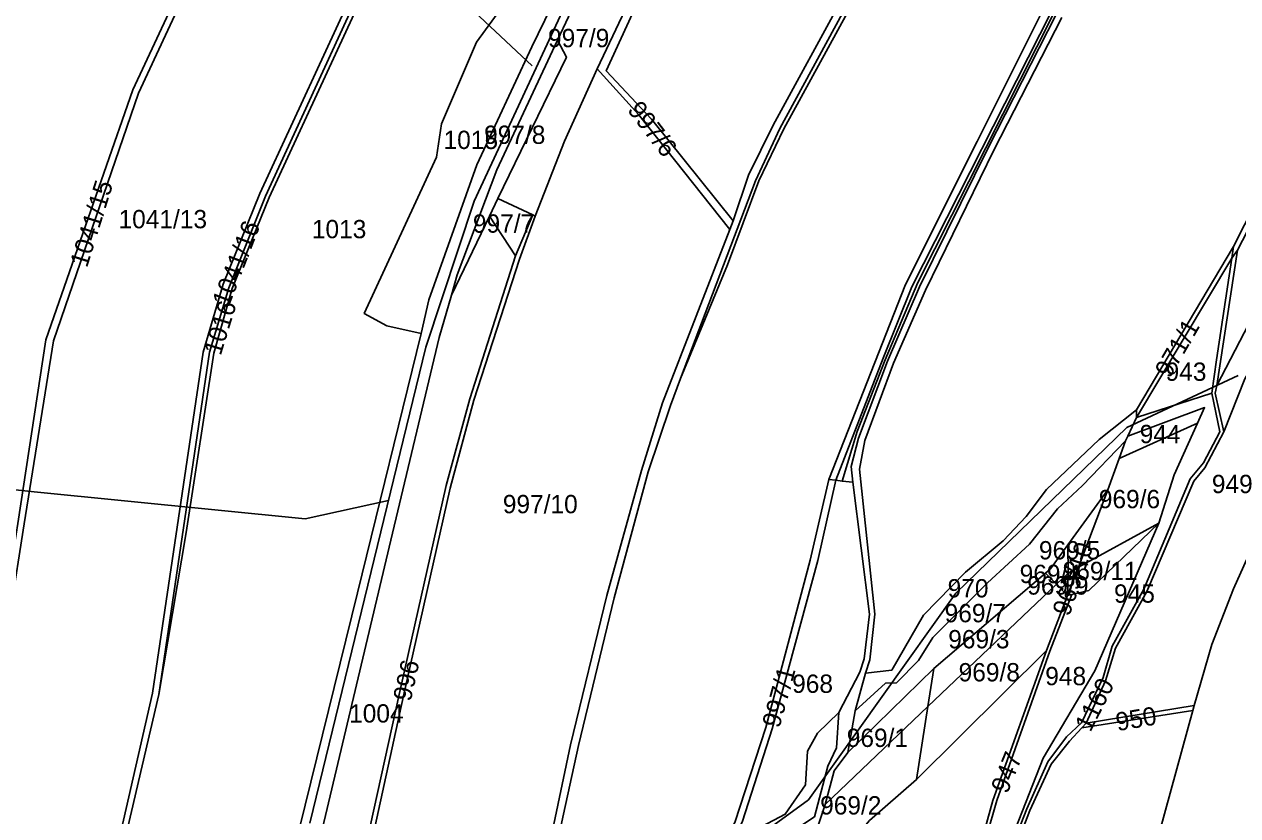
# Model space of a CAD drawing. Extents: x -623250 to -619626, y -1079612 to -1075424.
# Drawn here: x -622122 to -621459, y -1078639 to -1078207 of the extents above; entities that cross this region are included whole.
import ezdxf

# ---------------------------------------------------------------- set-up
doc = ezdxf.new("R2010")
doc.units = 0
for name, color, linetype in [('Cestní síť', 7, 'Continuous'), ('Parcela nároku', 7, 'Continuous'), ('Parcelní číslo', 7, 'Continuous'), ('Silnice III_35719', 7, 'Continuous'), ('Technická opateření liniová', 7, 'Continuous')]:
    doc.layers.add(name, color=color, linetype=linetype)

msp = doc.modelspace()

# ---------------------------------------------------------------- linework, layer by layer
at = {"layer": 'Cestní síť'}
for p, q in [((-621519.46, -1078427.24), (-621458.59, -1078398.76)), ((-621612.73, -1078517.62), (-621519.46, -1078427.24)), ((-622116.23, -1078462.32), (-622408.06, -1078432)), ((-621968.13, -1078477.07), (-622116.23, -1078462.32)), ((-621968.13, -1078477.07), (-621922.63, -1078467.15)), ((-621693.23, -1078630.58), (-621612.73, -1078517.62)), ((-621746.25, -1078668.89), (-621693.23, -1078630.58))]:
    msp.add_line(p, q, dxfattribs=at)
at = {"layer": 'Parcela nároku'}
for points in [[(-621287.56, -1077905.65), (-621340.92, -1078060.83), (-621413.47, -1078234.45), (-621461.2, -1078328.4), (-621462.02, -1078334.75), (-621459.02, -1078330.44), (-621410.27, -1078236.51), (-621337.32, -1078062), (-621284.16, -1077906.18), (-621257.6, -1077825.18), (-621204.75, -1077662.32), (-621198.6, -1077626.58), (-621199.7, -1077617.03), (-621206.08, -1077609.32), (-621211.44, -1077608.6), (-621204.6, -1077618.06), (-621201.95, -1077630.34), (-621208.08, -1077659.7), (-621260.76, -1077824.45)], [(-621364.39, -1077678.9), (-621360.94, -1077671.33), (-621356.07, -1077656.62), (-621361.81, -1077680.91), (-621375.21, -1077712.24), (-621395.2, -1077773.48), (-621413.63, -1077833.01), (-621448.87, -1077932.09), (-621484.15, -1078031.22), (-621531.47, -1078143.68), (-621559.31, -1078200.97), (-621633.61, -1078348.03), (-621651.3, -1078390.37), (-621666.67, -1078429.48), (-621674.85, -1078456.45), (-621678.32, -1078456.03), (-621652.48, -1078389.36), (-621636.77, -1078350.51), (-621560.48, -1078200.14), (-621532.5, -1078143.13), (-621485.18, -1078030.89), (-621450, -1077931.7), (-621414.98, -1077832.91), (-621377.7, -1077716.06)], [(-621536.14, -1078141.02), (-621489.42, -1078030.25), (-621424.75, -1077849.92), (-621379.95, -1077714.81), (-621377.7, -1077716.06), (-621414.98, -1077832.91), (-621450, -1077931.7), (-621485.18, -1078030.89), (-621532.5, -1078143.13), (-621560.48, -1078200.14), (-621636.77, -1078350.51), (-621652.48, -1078389.36), (-621678.32, -1078456.03), (-621682.14, -1078455.7), (-621640.24, -1078349.18), (-621601.13, -1078271)], [(-621722.01, -1078071.14), (-621688.22, -1078002.49), (-621678.81, -1077968.47), (-621662.8, -1077941.45), (-621649.7, -1077951.64), (-621639.49, -1077964.79), (-621623.87, -1077987.92), (-621612.61, -1077986.75), (-621607.21, -1077988.04), (-621600.75, -1078000.02), (-621600.73, -1078020.83), (-621618.53, -1078069.92), (-621649.86, -1078144.65), (-621673.38, -1078190.19), (-621712.52, -1078262.15), (-621725.93, -1078289.46), (-621734.43, -1078314.47), (-621779.01, -1078258.82), (-621803.7, -1078232.45), (-621772.94, -1078165.3)], [(-621817.29, -1077954.75), (-621820.07, -1077956.12), (-621837.79, -1077997.65), (-621875.7, -1078069.47), (-621917.7, -1078144.04), (-621989.81, -1078300.86), (-622009.81, -1078350.99), (-622020.37, -1078386.11), (-622048.13, -1078572.96), (-622033.09, -1078484.64), (-622018.08, -1078386.56), (-622007.96, -1078351.4), (-621987.87, -1078301.69), (-621915.38, -1078144.86), (-621873.83, -1078070.23), (-621835.8, -1077998.21)], [(-621830.83, -1078167.93), (-621842.45, -1078186.44), (-621849.93, -1078182.93), (-621874.57, -1078216.88), (-621893.72, -1078261.43), (-621896.45, -1078279.61), (-621935.88, -1078364.97), (-621923.56, -1078371.78), (-621904.78, -1078375.94), (-621900.59, -1078357.45), (-621874.38, -1078283.8), (-621844.4, -1078219.47), (-621798.7, -1078125.48)], [(-621800.25, -1078151.95), (-621830.24, -1078215.74), (-621825.45, -1078225.11), (-621862.83, -1078302.15), (-621843.79, -1078311.14), (-621842.49, -1078311.78), (-621826.5, -1078270.98), (-621808.67, -1078231.35), (-621776.45, -1078163.32)], [(-621779.01, -1078258.82), (-621734.43, -1078314.47), (-621736.18, -1078319.06), (-621786.12, -1078256.36), (-621808.67, -1078231.35), (-621776.45, -1078163.32), (-621772.94, -1078165.3), (-621803.7, -1078232.45)], [(-621830.24, -1078215.74), (-621863.53, -1078286.56), (-621885.08, -1078343.91), (-621888.3, -1078355.01), (-621867.46, -1078311.76), (-621862.83, -1078302.15), (-621825.45, -1078225.11)], [(-621851, -1078335.41), (-621875.98, -1078412.38), (-621889.02, -1078460.29), (-621914.51, -1078573.82), (-621939.52, -1078688.9), (-621916.93, -1078683.27), (-621862.33, -1078678.06), (-621842.5, -1078672.85), (-621836.88, -1078665.49), (-621823.3, -1078600.54), (-621803.29, -1078519.05), (-621784.46, -1078450.78), (-621772.93, -1078413.68), (-621736.18, -1078319.06), (-621786.12, -1078256.36), (-621808.67, -1078231.35), (-621826.5, -1078270.98), (-621842.49, -1078311.78)], [(-621340.16, -1078254.66), (-621336.49, -1078264.69), (-621353.63, -1078275.14), (-621364.04, -1078283.5), (-621372.09, -1078295.2), (-621389.85, -1078310.39), (-621432.54, -1078360.91), (-621455.01, -1078400.57), (-621466.37, -1078429.55), (-621471.07, -1078408.51), (-621470.26, -1078404.27), (-621452.78, -1078370.63), (-621435.04, -1078346.86), (-621398.92, -1078305.09), (-621366.28, -1078263.93), (-621348.2, -1078261.33)], [(-621364.04, -1078283.5), (-621372.09, -1078295.2), (-621389.85, -1078310.39), (-621432.54, -1078360.91), (-621455.01, -1078400.57), (-621466.37, -1078429.55), (-621476.8, -1078449.26), (-621482.83, -1078456.56), (-621508.49, -1078516.75), (-621525.64, -1078547.69), (-621530.97, -1078565.56), (-621541.52, -1078588.75), (-621482.56, -1078579.03), (-621472.93, -1078545.76), (-621461.05, -1078515.35), (-621436.88, -1078461.43), (-621371.42, -1078334.2), (-621356.58, -1078308.26), (-621336.49, -1078264.69), (-621353.63, -1078275.14)], [(-621862.83, -1078302.15), (-621843.79, -1078311.14), (-621853.26, -1078333.49), (-621867.46, -1078311.76)], [(-621894.99, -1078378.08), (-621921.42, -1078488.75), (-621962.09, -1078660.47), (-622002.29, -1078784.69), (-622011.88, -1078806.98), (-621978.6, -1078788.09), (-621955.11, -1078729.51), (-621942.41, -1078689.62), (-621916.87, -1078572.97), (-621891.12, -1078458.9), (-621878.16, -1078411.57), (-621853.26, -1078333.49), (-621867.46, -1078311.76), (-621888.3, -1078355.01)], [(-621843.79, -1078311.14), (-621842.49, -1078311.78), (-621851, -1078335.41), (-621875.98, -1078412.38), (-621889.02, -1078460.29), (-621914.51, -1078573.82), (-621939.52, -1078688.9), (-621942.41, -1078689.62), (-621916.87, -1078572.97), (-621891.12, -1078458.9), (-621878.16, -1078411.57), (-621853.26, -1078333.49)], [(-621514.12, -1078417.52), (-621461.2, -1078328.4), (-621462.02, -1078334.75), (-621514.13, -1078421.72)], [(-621462.02, -1078334.75), (-621514.13, -1078421.72), (-621472.9, -1078408.57), (-621470.31, -1078390.36)], [(-621520.06, -1078434.56), (-621518.84, -1078431.91), (-621476.94, -1078416.4), (-621480.77, -1078424.93), (-621523.55, -1078444.1)], [(-621514.12, -1078417.52), (-621534.4, -1078433.79), (-621563.17, -1078461.06), (-621574.29, -1078475.88), (-621586.92, -1078489.2), (-621607.54, -1078506.27), (-621630.42, -1078529.65), (-621647.78, -1078559.79), (-621662.04, -1078561.38), (-621667.75, -1078581.99), (-621651.12, -1078566.79), (-621645.23, -1078566.67), (-621633.23, -1078554.54), (-621625.24, -1078541.93), (-621595.52, -1078511.99), (-621572.58, -1078490.86), (-621557.2, -1078471.64), (-621543.56, -1078458.95), (-621520.06, -1078434.56), (-621518.84, -1078431.91), (-621514.13, -1078421.72)], [(-621523.55, -1078444.1), (-621480.77, -1078424.93), (-621493.43, -1078453.08), (-621501.89, -1078479.4), (-621545.81, -1078503.52), (-621529.84, -1078461.32)], [(-621633.23, -1078554.54), (-621625.24, -1078541.93), (-621595.52, -1078511.99), (-621572.58, -1078490.86), (-621557.2, -1078471.64), (-621543.56, -1078458.95), (-621520.06, -1078434.56), (-621523.55, -1078444.1), (-621529.84, -1078461.32), (-621551.55, -1078491.25), (-621561.1, -1078504.42), (-621563.8, -1078506.78), (-621624.8, -1078558.84), (-621671.66, -1078604.72), (-621667.75, -1078581.99), (-621651.12, -1078566.79), (-621645.23, -1078566.67)], [(-621716.55, -1078591.12), (-621692.39, -1078499.68), (-621682.14, -1078455.7), (-621678.32, -1078456.03), (-621688.19, -1078499.85), (-621713.01, -1078591.84), (-621729.26, -1078642.23), (-621734.51, -1078653.51), (-621736.66, -1078657.94), (-621756.17, -1078677.59), (-621760.1, -1078676.68), (-621740.16, -1078655.75), (-621733.53, -1078642.87)], [(-621678.32, -1078456.03), (-621688.19, -1078499.85), (-621713.01, -1078591.84), (-621729.26, -1078642.23), (-621734.51, -1078653.51), (-621705.92, -1078638.39), (-621694.79, -1078622.32), (-621693.69, -1078604.02), (-621688.23, -1078594.08), (-621676.74, -1078582.76), (-621665.21, -1078560.88), (-621662.89, -1078553.59), (-621659.96, -1078529.07), (-621668.93, -1078457.17), (-621674.85, -1078456.45)], [(-621551.55, -1078491.25), (-621529.84, -1078461.32), (-621545.81, -1078503.52), (-621551.43, -1078506.68)], [(-621561.49, -1078549.39), (-621549.33, -1078518.46), (-621540.21, -1078516.17), (-621501.89, -1078479.4), (-621536.85, -1078560.1), (-621565.04, -1078607.81), (-621588, -1078666.16), (-621596.96, -1078677.93), (-621608.54, -1078707.92), (-621609.68, -1078707.98), (-621601.6, -1078670.24), (-621590.34, -1078630.91)], [(-621501.89, -1078479.4), (-621545.81, -1078503.52), (-621551.69, -1078519.05), (-621549.33, -1078518.46), (-621540.21, -1078516.17)], [(-621551.43, -1078506.68), (-621551.55, -1078491.25), (-621561.1, -1078504.42), (-621563.8, -1078506.78), (-621557.84, -1078512.81)], [(-621563.8, -1078506.78), (-621557.84, -1078512.81), (-621628.01, -1078579.6), (-621624.8, -1078558.84)], [(-621551.43, -1078506.68), (-621557.84, -1078512.81), (-621551.69, -1078519.05)], [(-621545.81, -1078503.52), (-621551.43, -1078506.68), (-621551.69, -1078519.05)], [(-621628.01, -1078579.6), (-621634.19, -1078619.47), (-621563.27, -1078549.01), (-621551.69, -1078519.05), (-621557.84, -1078512.81)], [(-621551.69, -1078519.05), (-621549.33, -1078518.46), (-621561.49, -1078549.39), (-621590.34, -1078630.91), (-621601.6, -1078670.24), (-621609.68, -1078707.98), (-621611.72, -1078708.1), (-621603.36, -1078669.93), (-621592.52, -1078630.82), (-621563.27, -1078549.01)], [(-621659.89, -1078641.88), (-621634.19, -1078619.47), (-621563.27, -1078549.01), (-621592.52, -1078630.82), (-621603.36, -1078669.93), (-621611.72, -1078708.1), (-621622.67, -1078748.23), (-621659.71, -1078778.43), (-621673.47, -1078778.15), (-621677.73, -1078797.56), (-621660.27, -1078811.32), (-621677.88, -1078804.44), (-621679.12, -1078795.35), (-621676.5, -1078780.22), (-621707.18, -1078774.3), (-621699.61, -1078733.28), (-621701.12, -1078697.21), (-621697.9, -1078674.4), (-621679.48, -1078664.79)], [(-621671.66, -1078604.72), (-621624.8, -1078558.84), (-621628.01, -1078579.6), (-621684.21, -1078633.08), (-621679.27, -1078614.76)], [(-621693.69, -1078604.02), (-621694.79, -1078622.32), (-621705.92, -1078638.39), (-621734.51, -1078653.51), (-621736.66, -1078657.94), (-621737.8, -1078686.43), (-621713.91, -1078655.66), (-621689.88, -1078639.73), (-621682.64, -1078612.21), (-621678.01, -1078602.15), (-621676.74, -1078582.76), (-621688.23, -1078594.08)], [(-621684.21, -1078633.08), (-621697.9, -1078674.4), (-621679.48, -1078664.79), (-621659.89, -1078641.88), (-621634.19, -1078619.47), (-621628.01, -1078579.6)], [(-621541.52, -1078588.75), (-621543.87, -1078591.26), (-621483.31, -1078581.78), (-621482.56, -1078579.03)]]:
    msp.add_lwpolyline(points, close=True, dxfattribs=at)
for points in [[(-621554.92, -1078203.35), (-621592.05, -1078275.81), (-621629.4, -1078352.25), (-621646.81, -1078392.15), (-621662.54, -1078434.29), (-621665.37, -1078450.05), (-621657.03, -1078529.12), (-621659.7, -1078554.03), (-621662.04, -1078561.38), (-621647.78, -1078559.79), (-621630.42, -1078529.65), (-621607.54, -1078506.27), (-621586.92, -1078489.2), (-621574.29, -1078475.88), (-621563.17, -1078461.06), (-621534.4, -1078433.79), (-621514.12, -1078417.52), (-621461.2, -1078328.4), (-621413.47, -1078234.45), (-621340.92, -1078060.83)], [(-621270.05, -1078106.95), (-621312.71, -1078208.01), (-621327.26, -1078238.09), (-621340.16, -1078254.66), (-621348.2, -1078261.33), (-621366.28, -1078263.93), (-621398.92, -1078305.09), (-621435.04, -1078346.86), (-621452.78, -1078370.63), (-621470.26, -1078404.27), (-621459.02, -1078330.44), (-621410.27, -1078236.51), (-621337.32, -1078062)], [(-621798.7, -1078125.48), (-621844.4, -1078219.47), (-621874.38, -1078283.8), (-621900.59, -1078357.45), (-621904.78, -1078375.94), (-621939.56, -1078517.46), (-621974.55, -1078659.27), (-621985.66, -1078686.13), (-622011.55, -1078776.25), (-622019.48, -1078795.6), (-622050.66, -1078859.01), (-622055.18, -1078868.03), (-622113.39, -1078984.18), (-622171.75, -1079100.51)], [(-622009.77, -1078130.49), (-622062.34, -1078242.79), (-622109.78, -1078379.31), (-622125.1, -1078479.68), (-622132.38, -1078526.23), (-622145.98, -1078603.74), (-622157.37, -1078662.89), (-622204.46, -1078777.19), (-622250.94, -1078861.08), (-622263.63, -1078886.91), (-622341.05, -1078848.39), (-622252.06, -1078684.87), (-622238.99, -1078651.1), (-622232.5, -1078631.23), (-622214.83, -1078548.54), (-622204.5, -1078487.77), (-622195.3, -1078392.34), (-622186.11, -1078342.14), (-622164.43, -1078280.38), (-622123.52, -1078182.67)], [(-622009.77, -1078130.49), (-622062.34, -1078242.79), (-622109.78, -1078379.31), (-622125.1, -1078479.68), (-622132.38, -1078526.23), (-622145.98, -1078603.74), (-622157.37, -1078662.89), (-622204.46, -1078777.19), (-622250.94, -1078861.08), (-622263.63, -1078886.91), (-622260.65, -1078888.33), (-622247.8, -1078862.64), (-622201.27, -1078777.95), (-622154.33, -1078663.49), (-622142.85, -1078603.35), (-622129.1, -1078527.57), (-622121.6, -1078479.86), (-622105.64, -1078380), (-622059.07, -1078244.77), (-622006.23, -1078130.73)], [(-621920.88, -1078143.42), (-621992.93, -1078299.5), (-622012.94, -1078348.91), (-622023.83, -1078386.03), (-622051.57, -1078572.25), (-622075, -1078675.16), (-622093.94, -1078738.39), (-622132.06, -1078821.5), (-622164.4, -1078884.44), (-622184.48, -1078918.47), (-622193.37, -1078930.2), (-622224.32, -1078909.51), (-622245.47, -1078895.87), (-622260.65, -1078888.33), (-622247.8, -1078862.64), (-622201.27, -1078777.95), (-622154.33, -1078663.49), (-622142.85, -1078603.35), (-622129.1, -1078527.57), (-622121.6, -1078479.86), (-622105.64, -1078380), (-622059.07, -1078244.77), (-622006.23, -1078130.73)], [(-622132.06, -1078821.5), (-622093.94, -1078738.39), (-622075, -1078675.16), (-622051.57, -1078572.25), (-622023.83, -1078386.03), (-622012.94, -1078348.91), (-621992.93, -1078299.5), (-621920.88, -1078143.42)], [(-621917.7, -1078144.04), (-621989.81, -1078300.86), (-622009.81, -1078350.99), (-622020.37, -1078386.11), (-622048.13, -1078572.96), (-622072.14, -1078675.77), (-622091.03, -1078741.03), (-622128.19, -1078823.01)], [(-621915.38, -1078144.86), (-621987.87, -1078301.69), (-622007.96, -1078351.4), (-622018.08, -1078386.56), (-622033.09, -1078484.64), (-622048.13, -1078572.96), (-622072.14, -1078675.77), (-622091.03, -1078741.03), (-622128.19, -1078823.01)], [(-621536.14, -1078141.02), (-621601.13, -1078271), (-621640.24, -1078349.18), (-621682.14, -1078455.7), (-621692.39, -1078499.68), (-621716.55, -1078591.12), (-621733.53, -1078642.87), (-621740.16, -1078655.75), (-621760.1, -1078676.68), (-621831.78, -1078660.02), (-621818.81, -1078600.9), (-621799.45, -1078520.18), (-621780.85, -1078451.5), (-621768.67, -1078415.18), (-621763.22, -1078400.52), (-621737.43, -1078338.4), (-621720.36, -1078292.56), (-621706.68, -1078264.18), (-621667.8, -1078192.73)], [(-622158.74, -1079098.38), (-622110.04, -1079002.85), (-622107.93, -1078998.74), (-622042.21, -1078867.47), (-622011.88, -1078806.98), (-622002.29, -1078784.69), (-621962.09, -1078660.47), (-621921.42, -1078488.75), (-621894.99, -1078378.08), (-621888.3, -1078355.01), (-621885.08, -1078343.91), (-621863.53, -1078286.56), (-621830.24, -1078215.74), (-621800.25, -1078151.95)], [(-622142.01, -1078904.85), (-622085.75, -1078869.99), (-622065.84, -1078865.65), (-622050.66, -1078859.01), (-622019.48, -1078795.6), (-622011.55, -1078776.25), (-621985.66, -1078686.13), (-621974.55, -1078659.27), (-621939.56, -1078517.46), (-621904.78, -1078375.94), (-621923.56, -1078371.78), (-621935.88, -1078364.97), (-621896.45, -1078279.61), (-621893.72, -1078261.43), (-621874.57, -1078216.88), (-621849.93, -1078182.93)], [(-621673.38, -1078190.19), (-621712.52, -1078262.15), (-621725.93, -1078289.46), (-621734.43, -1078314.47), (-621736.18, -1078319.06), (-621772.93, -1078413.68), (-621784.46, -1078450.78), (-621803.29, -1078519.05), (-621823.3, -1078600.54), (-621836.88, -1078665.49), (-621838.04, -1078671.32), (-621833.28, -1078667.16), (-621831.78, -1078660.02), (-621818.81, -1078600.9), (-621799.45, -1078520.18), (-621780.85, -1078451.5), (-621768.67, -1078415.18), (-621763.22, -1078400.52), (-621722.25, -1078292.55), (-621708.86, -1078263.97), (-621670.16, -1078192.45)], [(-621246.01, -1078185.49), (-621266.68, -1078212.76), (-621275.63, -1078229.25), (-621289.76, -1078235.93), (-621307, -1078240.79), (-621324.7, -1078249.3), (-621330.24, -1078260.55), (-621336.49, -1078264.69), (-621356.58, -1078308.26), (-621371.42, -1078334.2), (-621436.88, -1078461.43), (-621461.05, -1078515.35), (-621472.93, -1078545.76), (-621482.56, -1078579.03), (-621483.31, -1078581.78), (-621513.7, -1078692.54), (-621522.18, -1078737.53), (-621523.53, -1078762.49), (-621529.55, -1078801.39), (-621550, -1078870.86), (-621596.99, -1078998.76), (-621655.34, -1079131.2)], [(-621670.16, -1078192.45), (-621708.86, -1078263.97), (-621722.25, -1078292.55), (-621763.22, -1078400.52), (-621737.43, -1078338.4), (-621720.36, -1078292.56), (-621706.68, -1078264.18), (-621667.8, -1078192.73)], [(-621554.92, -1078203.35), (-621592.05, -1078275.81), (-621629.4, -1078352.25), (-621646.81, -1078392.15), (-621662.54, -1078434.29), (-621665.37, -1078450.05), (-621657.03, -1078529.12), (-621659.7, -1078554.03), (-621662.04, -1078561.38), (-621667.75, -1078581.99), (-621671.66, -1078604.72), (-621679.27, -1078614.76), (-621684.21, -1078633.08), (-621697.9, -1078674.4)], [(-621689.88, -1078639.73), (-621682.64, -1078612.21), (-621678.01, -1078602.15), (-621676.74, -1078582.76), (-621665.21, -1078560.88), (-621662.89, -1078553.59), (-621659.96, -1078529.07), (-621668.93, -1078457.17), (-621669.86, -1078448.59), (-621665.85, -1078433.14), (-621650.14, -1078390.97), (-621632.57, -1078350.43), (-621595.12, -1078274.48), (-621557.95, -1078201.7)], [(-621557.95, -1078201.7), (-621595.12, -1078274.48), (-621632.57, -1078350.43), (-621650.14, -1078390.97), (-621665.85, -1078433.14), (-621669.86, -1078448.59), (-621668.93, -1078457.17), (-621674.85, -1078456.45), (-621666.67, -1078429.48), (-621651.3, -1078390.37), (-621633.61, -1078348.03), (-621559.31, -1078200.97)], [(-621586.67, -1078667.99), (-621573.93, -1078635.37), (-621562.59, -1078609.82), (-621552.3, -1078596.17), (-621544.11, -1078588.4), (-621532.28, -1078563.69), (-621527.31, -1078546.68), (-621510.04, -1078515.48), (-621484.85, -1078455.22), (-621477.53, -1078446.44), (-621468.49, -1078429.53), (-621472.9, -1078408.57), (-621470.31, -1078390.36), (-621462.02, -1078334.75), (-621459.02, -1078330.44), (-621470.26, -1078404.27), (-621471.07, -1078408.51), (-621466.37, -1078429.55), (-621476.8, -1078449.26), (-621482.83, -1078456.56), (-621508.49, -1078516.75), (-621525.64, -1078547.69), (-621530.97, -1078565.56), (-621541.52, -1078588.75), (-621543.87, -1078591.26), (-621550.67, -1078598.53), (-621560.77, -1078611.05), (-621572.26, -1078636.28), (-621584.71, -1078668.69)], [(-621586.67, -1078667.99), (-621573.93, -1078635.37), (-621562.59, -1078609.82), (-621552.3, -1078596.17), (-621544.11, -1078588.4), (-621532.28, -1078563.69), (-621527.31, -1078546.68), (-621510.04, -1078515.48), (-621484.85, -1078455.22), (-621477.53, -1078446.44), (-621468.49, -1078429.53), (-621472.9, -1078408.57), (-621514.13, -1078421.72), (-621518.84, -1078431.91), (-621476.94, -1078416.4), (-621480.77, -1078424.93), (-621493.43, -1078453.08), (-621501.89, -1078479.4), (-621536.85, -1078560.1), (-621565.04, -1078607.81), (-621588, -1078666.16)], [(-621513.7, -1078692.54), (-621483.31, -1078581.78), (-621543.87, -1078591.26), (-621550.67, -1078598.53), (-621560.77, -1078611.05), (-621572.26, -1078636.28), (-621584.71, -1078668.69)]]:
    msp.add_lwpolyline(points, dxfattribs=at)
at = {"layer": 'Silnice III_35719'}
for p, q in [((-621875.82, -1078303.64), (-621741.17, -1078013.99)), ((-621902.19, -1078383.36), (-621875.82, -1078303.64)), ((-621965.58, -1078643.26), (-621902.19, -1078383.36))]:
    msp.add_line(p, q, dxfattribs=at)
at = {"layer": 'Technická opateření liniová'}
msp.add_line((-621844.2, -1078229.72), (-622119.57, -1077971.37), dxfattribs=at)

# ---------------------------------------------------------------- texts
at = {"layer": 'Parcelní číslo'}
for s, p in [('997/9', (-621835.48, -1078219.59)), ('997/8', (-621870.41, -1078272.38)), ('1015', (-621892.55, -1078275.18)), ('1041/13', (-622070.06, -1078318.45)), ('997/7', (-621876.51, -1078320.87)), ('1013', (-621964.48, -1078323.89)), ('943', (-621498.19, -1078401.74)), ('944', (-621512.35, -1078435.79)), ('949', (-621472.94, -1078463.07)), ('997/10', (-621860.18, -1078474.05)), ('969/6', (-621534.66, -1078471.3)), ('969/5', (-621567.38, -1078499.25)), ('969/4', (-621577.92, -1078512.17)), ('969/11', (-621554.42, -1078510.55)), ('970', (-621617.24, -1078520.02)), ('969/9', (-621573.77, -1078518.48)), ('945', (-621526.36, -1078522.89)), ('969/7', (-621618.88, -1078533.58)), ('969/3', (-621616.91, -1078547.81)), ('969/8', (-621611.23, -1078565.86)), ('968', (-621702.17, -1078572.12)), ('948', (-621563.93, -1078567.96)), ('1004', (-621944.13, -1078588.34)), ('969/1', (-621672.34, -1078601.66)), ('969/2', (-621686.88, -1078638.54))]:
    msp.add_text(s, height=10, dxfattribs=at).set_placement(p)
for s, rotation, p in [('997/6', 307.36944, (-621792.54, -1078253.91)), ('1041/15', 72.68184, (-622087.28, -1078340.38)), ('1041/16', 68.85198, (-622009.92, -1078361.95)), ('1016', 72.8127, (-622014.28, -1078388.39)), ('971/1', 59.92119, (-621495.97, -1078400.86)), ('969/10', 71.07813, (-621550.82, -1078530.76)), ('996', 77.45319, (-621910.5, -1078577.23)), ('997/1', 74.44422, (-621709.15, -1078591.8)), ('1160', 63.33138, (-621539.27, -1078594.01)), ('950', 9.67824, (-621524.51, -1078593.06)), ('947', 67.8609, (-621584.69, -1078627.68))]:
    msp.add_text(s, height=10, rotation=rotation, dxfattribs=at).set_placement(p)

doc.saveas('drawing.dxf')
